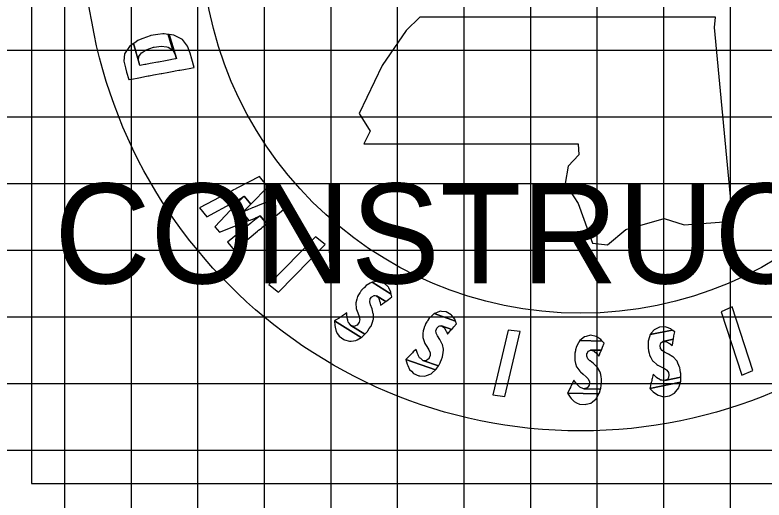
# Model space of a CAD drawing. Extents: x -10 to 342, y -5 to 215.
# Drawn here: x 323.25 to 334.51, y 185.25 to 192.53 of the extents above; entities that cross this region are included whole.
import ezdxf

# ---------------------------------------------------------------- set-up
doc = ezdxf.new("R2010")
doc.units = 0
for name, color, linetype in [('SHEET_CONSULTANT_STAMP', 7, 'Continuous'), ('SHEET_LOGO', 7, 'Continuous'), ('SHEET_LOGO_BG', 7, 'Continuous'), ('SHEET_PRELIM', 7, 'Continuous'), ('XS_SHEET_MAJOR_GRIDS', 7, 'Continuous'), ('XS_SHEET_MEDIUM_GRIDS', 7, 'Continuous'), ('XS_SHEET_MINOR_GRIDS', 7, 'Continuous')]:
    doc.layers.add(name, color=color, linetype=linetype)

msp = doc.modelspace()

# ---------------------------------------------------------------- linework, layer by layer
at = {"layer": 'SHEET_CONSULTANT_STAMP'}
msp.add_lwpolyline([(323.5, 185.5), (340, 185.5), (340, 202), (323.5, 202)], close=True, dxfattribs=at)
at = {"layer": 'SHEET_LOGO'}
for points in [[(329.333, 192.494), (329.127, 192.297), (328.766, 191.772), (328.422, 191.05), (328.585, 190.783), (328.49, 190.594), (331.715, 190.594), (331.724, 190.43), (331.561, 190.258), (331.518, 190), (331.715, 189.699), (331.93, 189.106), (332.154, 189.08), (332.429, 189.312), (333.005, 189.476), (333.306, 189.381), (334.037, 189.433), (333.762, 192.34), (333.779, 192.494)], [(325.553, 192.046), (325.621, 192.002), (325.551, 192.238), (325.494, 192.245), (325.472, 192.248), (325.395, 192.236), (325.29, 192.22), (325.279, 192.216), (325.171, 192.176), (325.107, 192.153), (325.095, 192.144), (325.05, 192.113), (325.05, 192.113), (325.032, 192.101), (325.03, 192.099), (325.118, 191.803), (325.106, 191.851), (325.112, 191.906), (325.15, 191.96), (325.163, 191.968), (325.222, 192.007), (325.33, 192.045), (325.341, 192.046), (325.447, 192.061), (325.531, 192.049)], [(325.943, 191.742), (325.944, 191.742), (325.907, 191.866), (325.88, 191.956), (325.841, 192.06), (325.766, 192.16), (325.635, 192.227), (325.567, 192.235), (325.675, 191.874), (325.675, 191.874), (325.66, 191.871), (325.608, 191.861), (325.588, 191.857), (325.512, 191.843), (325.408, 191.823), (325.397, 191.821), (325.283, 191.8), (325.216, 191.787), (325.202, 191.785), (325.151, 191.775), (325.13, 191.771), (325.128, 191.771), (325.03, 192.099), (324.971, 192.058), (324.895, 191.944), (324.886, 191.837), (324.909, 191.735), (324.928, 191.669), (324.96, 191.56), (324.961, 191.56), (324.968, 191.561), (325.007, 191.568), (325.111, 191.588), (325.179, 191.6), (325.181, 191.601), (325.202, 191.604), (325.253, 191.614), (325.267, 191.617), (325.334, 191.629), (325.447, 191.65), (325.459, 191.652), (325.563, 191.672), (325.639, 191.686), (325.659, 191.689), (325.711, 191.699), (325.726, 191.702), (325.726, 191.702), (325.788, 191.713), (325.893, 191.733), (325.936, 191.741)], [(325.621, 192.001), (325.656, 191.938), (325.567, 192.236), (325.551, 192.238)], [(325.656, 191.938), (325.675, 191.874), (325.567, 192.235), (325.567, 192.236)], [(326.435, 189.85), (326.024, 189.636), (326.133, 189.502), (326.541, 189.72), (326.56, 189.73), (326.566, 189.733), (326.566, 189.734), (326.568, 189.735), (326.568, 189.735), (326.606, 189.757), (326.613, 189.76), (326.625, 189.767), (326.628, 189.769), (326.629, 189.769), (326.63, 189.77), (326.672, 189.796), (326.676, 189.799), (326.696, 189.811), (326.794, 189.69), (327.049, 189.952), (326.924, 190.105), (326.595, 189.934), (326.575, 189.924), (326.57, 189.921), (326.526, 189.898), (326.525, 189.897), (326.524, 189.897), (326.521, 189.895), (326.509, 189.889), (326.502, 189.885), (326.462, 189.865), (326.46, 189.864), (326.454, 189.86)], [(326.57, 189.684), (326.255, 189.352), (326.323, 189.268), (326.765, 189.443), (326.667, 189.565), (326.682, 189.579), (326.687, 189.584), (326.689, 189.586), (326.72, 189.616), (326.726, 189.622), (326.736, 189.631), (326.738, 189.634), (326.739, 189.635), (326.74, 189.635), (326.774, 189.67), (326.778, 189.674), (326.794, 189.69), (326.696, 189.811), (326.679, 189.795), (326.676, 189.792), (326.641, 189.757), (326.64, 189.756), (326.639, 189.755), (326.636, 189.753), (326.627, 189.743), (326.622, 189.738), (326.591, 189.706), (326.589, 189.705), (326.584, 189.699)], [(326.686, 189.575), (326.667, 189.565), (326.765, 189.443), (326.786, 189.452), (326.786, 189.452), (326.793, 189.454), (326.795, 189.455), (326.837, 189.472), (326.845, 189.475), (326.845, 189.475), (326.858, 189.48), (326.858, 189.481), (326.861, 189.482), (326.863, 189.482), (326.864, 189.483), (326.864, 189.483), (326.909, 189.504), (326.914, 189.507), (326.935, 189.517), (327.031, 189.398), (327.309, 189.632), (327.185, 189.785), (326.833, 189.641), (326.812, 189.633), (326.807, 189.63), (326.76, 189.61), (326.759, 189.61), (326.758, 189.609), (326.754, 189.608), (326.742, 189.602), (326.734, 189.599), (326.695, 189.579), (326.692, 189.578)], [(326.795, 189.407), (326.444, 189.119), (326.547, 188.992), (326.895, 189.284), (326.911, 189.298), (326.916, 189.302), (326.918, 189.304), (326.918, 189.304), (326.952, 189.332), (326.958, 189.337), (326.968, 189.345), (326.97, 189.348), (326.971, 189.348), (326.972, 189.349), (327.01, 189.381), (327.014, 189.384), (327.031, 189.398), (326.935, 189.517), (326.917, 189.503), (326.913, 189.5), (326.874, 189.471), (326.873, 189.47), (326.872, 189.469), (326.869, 189.467), (326.859, 189.459), (326.852, 189.454), (326.818, 189.427), (326.816, 189.425), (326.811, 189.421)], [(327.768, 189.198), (327.067, 188.484), (327.21, 188.371), (327.911, 189.085)], [(328.65, 188.524), (328.618, 188.52), (328.904, 188.34), (328.898, 188.368), (328.867, 188.434), (328.862, 188.444), (328.796, 188.506), (328.796, 188.506), (328.732, 188.526), (328.711, 188.532)], [(328.347, 187.854), (328.297, 187.869), (328.507, 187.737), (328.517, 187.747), (328.523, 187.752), (328.538, 187.767), (328.545, 187.778), (328.554, 187.791), (328.574, 187.822), (328.597, 187.856), (328.6, 187.861), (328.61, 187.887), (328.622, 187.92), (328.634, 187.954), (328.635, 187.965), (328.636, 188.037), (328.634, 188.046), (328.616, 188.118), (328.592, 188.18), (328.592, 188.181), (328.581, 188.224), (328.586, 188.265), (328.588, 188.269), (328.607, 188.295), (328.607, 188.296), (328.609, 188.298), (328.612, 188.3), (328.645, 188.319), (328.66, 188.318), (328.66, 188.318), (328.684, 188.316), (328.821, 188.23), (328.862, 188.259), (328.912, 188.297), (328.904, 188.34), (328.617, 188.52), (328.586, 188.502), (328.529, 188.469), (328.495, 188.435), (328.487, 188.427), (328.482, 188.422), (328.457, 188.397), (328.455, 188.395), (328.453, 188.393), (328.436, 188.365), (328.433, 188.361), (328.414, 188.33), (328.398, 188.303), (328.398, 188.302), (328.387, 188.262), (328.373, 188.21), (328.373, 188.202), (328.379, 188.126), (328.384, 188.111), (328.401, 188.059), (328.42, 188.006), (328.428, 187.969), (328.43, 187.961), (328.421, 187.917), (328.4, 187.888), (328.39, 187.875), (328.377, 187.868), (328.355, 187.858)], [(328.736, 188.214), (328.743, 188.172), (328.771, 188.193), (328.773, 188.194), (328.777, 188.197), (328.806, 188.218), (328.812, 188.223), (328.812, 188.223), (328.821, 188.23), (328.684, 188.316), (328.716, 188.283), (328.719, 188.273), (328.735, 188.223), (328.736, 188.218)], [(329.582, 188.061), (329.551, 188.05), (329.869, 187.936), (329.858, 187.963), (329.812, 188.021), (329.806, 188.029), (329.728, 188.075), (329.728, 188.075), (329.661, 188.081), (329.64, 188.082)], [(333.862, 188.073), (334.17, 187.121), (334.337, 187.195), (334.028, 188.147)], [(328.067, 187.948), (328.053, 187.938), (328.45, 187.688), (328.466, 187.697), (328.507, 187.737), (328.297, 187.869), (328.271, 187.902), (328.258, 187.919), (328.25, 187.948), (328.246, 187.965), (328.241, 187.988), (328.238, 188.033), (328.237, 188.057), (328.218, 188.045), (328.185, 188.024), (328.169, 188.014), (328.158, 188.006), (328.139, 187.994), (328.132, 187.989), (328.119, 187.981)], [(329.431, 187.341), (329.379, 187.346), (329.612, 187.262), (329.62, 187.274), (329.624, 187.28), (329.636, 187.298), (329.64, 187.31), (329.646, 187.325), (329.659, 187.359), (329.674, 187.397), (329.676, 187.403), (329.68, 187.431), (329.685, 187.466), (329.69, 187.501), (329.687, 187.512), (329.673, 187.583), (329.669, 187.591), (329.636, 187.657), (329.6, 187.713), (329.599, 187.714), (329.579, 187.754), (329.575, 187.794), (329.577, 187.798), (329.589, 187.829), (329.589, 187.829), (329.59, 187.831), (329.593, 187.834), (329.621, 187.861), (329.636, 187.862), (329.636, 187.862), (329.66, 187.865), (329.812, 187.811), (329.845, 187.849), (329.887, 187.896), (329.869, 187.936), (329.551, 188.05), (329.524, 188.026), (329.475, 187.981), (329.449, 187.941), (329.443, 187.931), (329.44, 187.926), (329.421, 187.896), (329.419, 187.893), (329.417, 187.89), (329.407, 187.859), (329.405, 187.855), (329.393, 187.82), (329.383, 187.791), (329.383, 187.79), (329.381, 187.748), (329.378, 187.695), (329.381, 187.687), (329.403, 187.614), (329.411, 187.601), (329.439, 187.554), (329.469, 187.506), (329.485, 187.471), (329.488, 187.464), (329.49, 187.42), (329.475, 187.386), (329.468, 187.371), (329.457, 187.362), (329.438, 187.347)], [(328.119, 187.707), (328.191, 187.657), (328.204, 187.653), (328.276, 187.632), (328.304, 187.635), (328.374, 187.645), (328.392, 187.655), (328.45, 187.688), (328.053, 187.938), (328.054, 187.867), (328.06, 187.842), (328.074, 187.78), (328.095, 187.746)], [(329.733, 187.777), (329.748, 187.737), (329.771, 187.764), (329.773, 187.766), (329.776, 187.769), (329.8, 187.797), (329.805, 187.802), (329.805, 187.802), (329.812, 187.811), (329.66, 187.865), (329.698, 187.84), (329.703, 187.831), (329.73, 187.785), (329.732, 187.781)], [(330.66, 187.8), (330.431, 186.826), (330.612, 186.803), (330.841, 187.777)], [(333.06, 187.065), (333.013, 187.041), (333.256, 187.091), (333.257, 187.105), (333.257, 187.112), (333.258, 187.134), (333.256, 187.146), (333.253, 187.162), (333.246, 187.198), (333.239, 187.238), (333.238, 187.244), (333.227, 187.27), (333.213, 187.302), (333.199, 187.335), (333.191, 187.343), (333.143, 187.396), (333.135, 187.401), (333.072, 187.441), (333.012, 187.47), (333.011, 187.47), (332.973, 187.494), (332.949, 187.526), (332.948, 187.531), (332.943, 187.563), (332.943, 187.563), (332.943, 187.566), (332.944, 187.57), (332.954, 187.607), (332.966, 187.616), (332.965, 187.616), (332.985, 187.631), (333.143, 187.663), (333.152, 187.713), (333.163, 187.775), (333.127, 187.8), (332.795, 187.733), (332.785, 187.698), (332.766, 187.634), (332.765, 187.586), (332.765, 187.575), (332.765, 187.569), (332.764, 187.534), (332.764, 187.53), (332.764, 187.527), (332.771, 187.495), (332.772, 187.49), (332.78, 187.455), (332.786, 187.424), (332.787, 187.424), (332.807, 187.387), (332.832, 187.34), (332.838, 187.334), (332.896, 187.283), (332.909, 187.276), (332.958, 187.25), (333.008, 187.225), (333.039, 187.203), (333.046, 187.199), (333.07, 187.162), (333.075, 187.126), (333.077, 187.109), (333.072, 187.096), (333.063, 187.073)], [(332.816, 187.758), (332.796, 187.733), (333.127, 187.8), (333.103, 187.817), (333.035, 187.843), (333.025, 187.847), (332.935, 187.846), (332.935, 187.846), (332.874, 187.816), (332.855, 187.806)], [(331.85, 186.932), (331.799, 186.919), (332.047, 186.915), (332.051, 186.929), (332.053, 186.936), (332.058, 186.957), (332.058, 186.969), (332.059, 186.986), (332.061, 187.022), (332.063, 187.063), (332.063, 187.069), (332.057, 187.096), (332.051, 187.131), (332.044, 187.166), (332.038, 187.176), (332.002, 187.238), (331.996, 187.245), (331.943, 187.297), (331.891, 187.338), (331.89, 187.339), (331.858, 187.37), (331.841, 187.407), (331.841, 187.412), (331.844, 187.444), (331.843, 187.444), (331.844, 187.447), (331.846, 187.451), (331.864, 187.485), (331.877, 187.491), (331.877, 187.491), (331.899, 187.501), (332.061, 187.499), (332.08, 187.545), (332.104, 187.603), (332.074, 187.636), (331.736, 187.642), (331.718, 187.61), (331.686, 187.552), (331.675, 187.505), (331.672, 187.494), (331.671, 187.488), (331.662, 187.454), (331.662, 187.45), (331.661, 187.447), (331.661, 187.415), (331.661, 187.41), (331.661, 187.373), (331.661, 187.343), (331.661, 187.342), (331.672, 187.301), (331.687, 187.25), (331.692, 187.243), (331.737, 187.181), (331.748, 187.171), (331.79, 187.136), (331.833, 187.1), (331.859, 187.072), (331.865, 187.066), (331.881, 187.025), (331.877, 186.989), (331.876, 186.972), (331.868, 186.96), (331.855, 186.939)], [(331.762, 187.662), (331.736, 187.642), (332.074, 187.636), (332.055, 187.657), (331.993, 187.698), (331.985, 187.703), (331.896, 187.722), (331.896, 187.722), (331.831, 187.706), (331.81, 187.701)], [(333.093, 187.594), (333.127, 187.567), (333.133, 187.602), (333.133, 187.605), (333.134, 187.609), (333.14, 187.645), (333.141, 187.652), (333.141, 187.652), (333.143, 187.663), (332.985, 187.631), (333.031, 187.629), (333.039, 187.624), (333.086, 187.599), (333.09, 187.596)], [(329.137, 187.373), (329.125, 187.36), (329.567, 187.202), (329.581, 187.214), (329.612, 187.262), (329.379, 187.346), (329.347, 187.372), (329.329, 187.386), (329.316, 187.413), (329.308, 187.428), (329.298, 187.45), (329.286, 187.492), (329.279, 187.516), (329.263, 187.5), (329.235, 187.472), (329.223, 187.459), (329.213, 187.45), (329.197, 187.433), (329.191, 187.427), (329.181, 187.417)], [(331.996, 187.442), (332.024, 187.409), (332.037, 187.441), (332.038, 187.444), (332.04, 187.448), (332.054, 187.482), (332.056, 187.488), (332.056, 187.488), (332.061, 187.499), (331.899, 187.501), (331.943, 187.49), (331.951, 187.483), (331.991, 187.448), (331.994, 187.444)], [(329.24, 187.148), (329.321, 187.115), (329.335, 187.114), (329.41, 187.109), (329.436, 187.119), (329.502, 187.143), (329.517, 187.157), (329.567, 187.202), (329.125, 187.36), (329.142, 187.291), (329.153, 187.268), (329.18, 187.21), (329.208, 187.182)], [(332.793, 186.939), (332.789, 186.922), (333.249, 187.016), (333.254, 187.033), (333.256, 187.091), (333.013, 187.041), (332.972, 187.047), (332.95, 187.05), (332.925, 187.066), (332.91, 187.075), (332.891, 187.088), (332.858, 187.119), (332.84, 187.136), (332.835, 187.114), (332.825, 187.075), (332.821, 187.057), (332.818, 187.044), (332.813, 187.022), (332.811, 187.014), (332.807, 186.999)], [(331.562, 186.867), (331.554, 186.852), (332.024, 186.844), (332.033, 186.859), (332.047, 186.915), (331.799, 186.919), (331.76, 186.933), (331.739, 186.941), (331.718, 186.963), (331.706, 186.975), (331.69, 186.992), (331.664, 187.028), (331.65, 187.049), (331.64, 187.029), (331.623, 186.993), (331.615, 186.976), (331.609, 186.964), (331.599, 186.944), (331.596, 186.936), (331.589, 186.923)], [(332.997, 186.8), (333.083, 186.814), (333.095, 186.82), (333.162, 186.855), (333.18, 186.877), (333.224, 186.932), (333.23, 186.951), (333.249, 187.016), (332.789, 186.922), (332.839, 186.872), (332.86, 186.857), (332.914, 186.822), (332.952, 186.812)], [(331.731, 186.688), (331.818, 186.682), (331.832, 186.686), (331.905, 186.705), (331.926, 186.723), (331.981, 186.767), (331.991, 186.785), (332.024, 186.844), (331.555, 186.852), (331.592, 186.791), (331.61, 186.773), (331.655, 186.727), (331.69, 186.709)]]:
    msp.add_lwpolyline(points, close=True, dxfattribs=at)
for radius in [7.464, 5.697]:
    msp.add_circle((331.75, 193.75), radius, dxfattribs=at)
at = {"layer": 'SHEET_LOGO_BG'}
msp.add_lwpolyline([(323.5, 185.5), (340, 185.5), (340, 202), (323.5, 202)], close=True, dxfattribs=at)
at = {"layer": 'SHEET_PRELIM'}
msp.add_lwpolyline([(323.5, 185.5), (340, 185.5), (340, 202), (323.5, 202)], close=True, dxfattribs=at)
at = {"layer": 'XS_SHEET_MAJOR_GRIDS'}
for p, q in [((330, 0), (330, 202)), ((5, 190), (340, 190))]:
    msp.add_line(p, q, dxfattribs=at)
at = {"layer": 'XS_SHEET_MEDIUM_GRIDS'}
msp.add_line((325, 0), (325, 202), dxfattribs=at)
at = {"layer": 'XS_SHEET_MINOR_GRIDS'}
for p, q in [((324, 0), (324, 202)), ((326, 0), (326, 202)), ((327, 0), (327, 202)), ((328, 0), (328, 202)), ((329, 0), (329, 202)), ((331, 5), (331, 202)), ((332, 5), (332, 202)), ((333, 5), (333, 202)), ((334, 5), (334, 202)), ((5, 192), (340, 192)), ((5, 191), (340, 191)), ((5, 189), (340, 189)), ((5, 188), (340, 188)), ((5, 187), (340, 187)), ((5, 186), (340, 186))]:
    msp.add_line(p, q, dxfattribs=at)

# ---------------------------------------------------------------- texts
at = {"layer": 'SHEET_PRELIM'}
msp.add_text('CONSTRUCTION', height=1.5, dxfattribs=at).set_placement((323.84, 188.5))

doc.saveas('drawing.dxf')
